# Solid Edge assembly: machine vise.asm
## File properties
Author: Robert a Rhodes jr
Template: Normal.asm
Last saved by: CADCIM
Revision: 24
Application: Solid Edge
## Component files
slide key.par
base.par
Sliding jaw.par
vise screw.par
collar.par
handle rod.par
handle ball.par
jaw plate.par
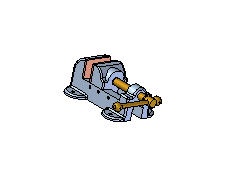
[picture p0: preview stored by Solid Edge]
